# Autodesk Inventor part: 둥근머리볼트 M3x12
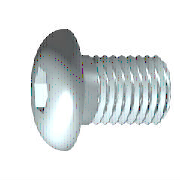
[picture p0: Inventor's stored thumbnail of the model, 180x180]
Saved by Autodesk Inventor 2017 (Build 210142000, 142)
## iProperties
IsCustomPart: 0
Created: 2012-02
Part Number: 둥근머리볼트 M3x12
Material: 강철
Description: 6각 소켓 버튼 머리 나사 - 제품 등급 A
Document SubType Name: Modeling
Standard: ISO 7380
Designer: mduedu
Standard Revision: Third edition 2004-01-15
Standards Organization: ISO
Language: ko-KR
Size Designation: M3 x 12
Categories: <MemberInstance><Categories><Category DisplayName="조임쇠" InternalName="e4da775c-781d-43d5-af7c-5136215cf5a6" Mnemonic="FSTN"><Category DisplayName="볼트" InternalN
Density: 7.85 g/cm^3
Mass: 0.90169 g
Surface Area: 1.87531 cm^2
Volume: 0.114865 cm^3
Appearance: 강철
Author: mduedu
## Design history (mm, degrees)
sketch "스케치1"
  geometry: L1 (0.057, 0)-(12, 0); L2 (12, 0)-(12, 1.5); L3 (12, 1.5)-(1, 1.5); L4 (1, 1.5)-(0.693, 1.5); L5 (0.693, 1.5)-(0, 1.5); L6 (0, 1.5)-(0, 2.85); L7 (0, 2.85)-(-1.65, 2.85); L8 (-1.65, 2.85)-(-1.65, 1.155); L9 (-1.65, 1.155)-(-0.61, 1.155); L10 (-0.61, 1.155)-(0.057, 0); L11 (-4.38, 0)-(14.73, 0) reference; L12 (0, -0.57)-(0, 3.42) reference; L13 (1, 1.5)-(0, 1.5)
  constraints: 22 end point, 6 parallel, 2 collinear, 2 perpendicular, 1 horizontal, 1 point on line
  dimensions: "d1" = 11 distance from line of L3.end L2 (= GEL); "d2" = 0.30683 distance of L4.end L3.end (computed from GAL); "d3" = 1.65 distance between parallel lines of L8 L6 (= KOH); "d4" = 1.04 distance of L8.end L9.end (= INTI); "d5" = 60 deg angle of L10 L1; "d6" = 3 diameter of L3 L1 (= GD); "d7" = 3 diameter of L5 L1 (= BDM); "d8" = 2.3094 diameter of L9 L1 (= 1.1547 x SW); "d9" = 5.7 diameter of L7 L1 (= KOD); "d26" = 12 distance between parallel lines of L12 L2 (= NLG)
revolve "본체" sketch "스케치1" stored, may be unused: angle "d10" = 90 deg
sketch "스케치2"
  geometry: L1 (0, -3.99)-(0, 3.99) reference; L2 (-3.99, 0)-(3.99, 0) reference; L3 (1.155, 0)-(0.577, -1); L4 (0.577, -1)-(-0.577, -1); L5 (-0.577, -1)-(-1.155, 0); L6 (-1.155, 0)-(-0.577, 1); L7 (-0.577, 1)-(0.577, 1); L8 (0.577, 1)-(1.155, 0); 2 further points
  constraints: 12 end point, 1 coincident, 1 horizontal alignment, 1 point on line, 12 other
extrude "슬롯" join sketch "스케치2" stored distance "d11" = 10; taper "d12" = 0 deg
workplane "Work Plane1"
body "Solid1"
fillet "모깎기1" dims "d17" = 1.45 (= RR)
feature "스레드" dims "d13" = 11 (= GEL), "d14" = 0
chamfer "모따기1" distance "d15" = 0.30673 (= -0.5 x SPD + 0.5 x GD); stored, may be unused: second distance "d16" = 0.30673 (= GUL), angle "d27" = 45 deg
fillet "모깎기2" dims "d30" = 0.1 (= R)
other parameters: "GD" = 3 (= NND) [user parameter; used in 2 equation terms], "NLG" = 12 [user parameter; used in 1 equation term], "GEL" = 11 [user parameter; used in 2 equation terms], "KOD" = 5.7 [user parameter; used in 1 equation term], "KOH" = 1.65 [user parameter; used in 1 equation term], "INTI" = 1.04 [user parameter; used in 1 equation term], "GAL" = 0.30673 (= 0.61345 x PTC) [user parameter; used in 1 equation term], "GUL" = 0.30673 (= 0.61345 x PTC) [user parameter; used in 1 equation term], "BDM" = 3 (= NND) [user parameter; used in 1 equation term], "SW" = 2 [user parameter; used in 1 equation term], "RR" = 1.45 [user parameter; used in 1 equation term], "SPD" = 2.38655 (= NND - 1.2269 x PTC) [user parameter; used in 1 equation term], "d19" = 0, "d28" = 0, "d29" = 0, "R" = 0.1 [user parameter; used in 1 equation term], "TOA" = 30 deg [user parameter], "GD1" = 2.38655 (= THREADDIA - 1.2269 x PTC) [user parameter], "THREADDIA" = 3 [user parameter; used in 1 equation term], "PTC" = 0.5 [user parameter; used in 5 equation terms], "NND" = 3 [user parameter; used in 3 equation terms], "KOH1" = 0.2 [user parameter], "E0" = 2.31 [user parameter]
